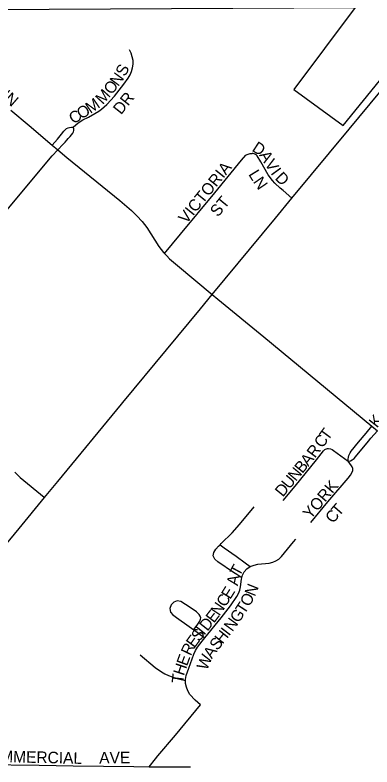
# Model space of a CAD drawing. Extents: x -51392 to 1635000, y 156707 to 696232.
# Drawn here: x 142661 to 144200, y 489969 to 493217 of the extents above; entities that cross this region are included whole.
import ezdxf

# ---------------------------------------------------------------- set-up
doc = ezdxf.new("R2010")
doc.units = 0
for name, color, linetype in [('GM_X_City_Street', 7, 'Continuous'), ('GM_X_City_Street_Text', 7, 'Continuous'), ('GM_X_Corporation', 7, 'Continuous'), ('GM_X_US_Route', 7, 'Continuous')]:
    doc.layers.add(name, color=color, linetype=linetype)

msp = doc.modelspace()

# ---------------------------------------------------------------- linework, layer by layer
at = {"layer": 'GM_X_City_Street'}
for points in [[(142911.9, 492732.6), (142933.5, 492751.4), (142953.3, 492763.8), (142976.8, 492776.3), (143005.2, 492792), (143021.4, 492801.8), (143033.6, 492810.4), (143045.3, 492820), (143056.6, 492830.8), (143089.3, 492866.8), (143129.5, 492917.7), (143148.3, 492944), (143156.4, 492958.1), (143163, 492972.8), (143167.7, 492988.3), (143170.1, 493004.3), (143170, 493013.2), (143169.5, 493020.5), (143166.3, 493036.3), (143160.9, 493051.6), (143154.2, 493066.3)], [(142643.1, 492805.5), (142720.8, 492739.1), (142821.3, 492654.7)], [(142821.3, 492654.7), (142843.4, 492681.1), (142861.3, 492702.6), (142871.2, 492715), (142877.2, 492721.2), (142882.9, 492726.9), (142890.1, 492729.6), (142896, 492731.1), (142904.2, 492732.5), (142911.9, 492732.6)], [(142845.6, 492634.5), (142866.8, 492657.4), (142876.5, 492667.8), (142884.5, 492676.7), (142890.1, 492682.9), (142898.7, 492692.1), (142909.9, 492706.3), (142913, 492712.6), (142913.4, 492718.5), (142913.8, 492725.8), (142911.9, 492732.6)], [(141933.2, 491622.4), (141984, 491665.8), (142095.8, 491762.2), (142156.8, 491817.3), (142191.3, 491852.7), (142245.3, 491914.6), (142422.5, 492129.9), (142610.7, 492357.2), (142821, 492608.8), (142845.6, 492634.5)], [(142821.3, 492654.7), (142845.6, 492634.5)], [(142845.6, 492634.5), (142883.9, 492602.1), (143112.6, 492415.8), (143162.5, 492372.8), (143186.2, 492349.8), (143208.3, 492325.1), (143228.6, 492299.1), (143280.5, 492216.6), (143300.6, 492191.1), (143305.1, 492186.7)], [(143305.1, 492186.7), (143374.5, 492270.2), (143522.4, 492448.9), (143637.5, 492590.5), (143656.3, 492611.4), (143661.2, 492614.6), (143665.7, 492616.6), (143674.3, 492618.8), (143682.8, 492619.1)], [(143854.8, 492426.5), (143816.6, 492458.7), (143804.5, 492468.9), (143781.4, 492490.3), (143771, 492501.9), (143752.6, 492527.2), (143721.1, 492582.7), (143705.1, 492608.1), (143702.1, 492611.7), (143697.8, 492614.7), (143691.9, 492617), (143686.9, 492618.3), (143682.8, 492619.1)], [(143305.1, 492186.7), (143315.1, 492176.9), (143327.1, 492164.6), (143360.9, 492134.7), (143510.6, 492009.8)], [(143510.6, 492009.8), (143535.8, 491989.2), (143734.2, 491826.8), (144199, 491441.5)], [(144097.9, 491289.6), (144097.6, 491299.2), (144098.9, 491307.3), (144100.8, 491315.1), (144105.4, 491325.4), (144110.5, 491333.3), (144141.4, 491371.4), (144175.3, 491410.6), (144199, 491441.5)], [(144199, 491441.5), (144223.7, 491420.8)], [(144097.9, 491289.6), (144107, 491291.7), (144115.2, 491295.4), (144119.2, 491298.1), (144123.7, 491301.7), (144129.1, 491308.4), (144185, 491376.8), (144195.2, 491389.3), (144223.7, 491420.8)], [(143816.4, 491120.2), (143868.8, 491182.3), (143961.1, 491295.7), (143991.2, 491334.1), (143996.7, 491340.2), (143999.6, 491342.2), (144003.8, 491343.7), (144008.3, 491344.5), (144012.7, 491344.8), (144020.6, 491343.5), (144027.9, 491340.7), (144034.2, 491335.8), (144097.9, 491289.6)], [(143936.7, 491025.2), (144010.2, 491115), (144096.8, 491216.3), (144106.9, 491229.2), (144114.8, 491243.1), (144116.8, 491250.4), (144117.2, 491254.2), (144117.2, 491258), (144114.6, 491265.1), (144111.2, 491270.5), (144097.9, 491289.6)], [(142659.2, 491242.7), (142682.9, 491219.7), (142785.5, 491134.7), (142788.1, 491132.6)], [(143544.7, 490929.2), (143549.7, 490934), (143596.9, 490979.9), (143629.2, 491017.2), (143692.3, 491093.3)], [(143675.1, 490835.1), (143675.3, 490835.2), (143691.4, 490841.2), (143708, 490844.5), (143756.5, 490849.7), (143771.7, 490853.3), (143785.8, 490859), (143798.4, 490867.4), (143809.6, 490878.1), (143861, 490941), (143871.6, 490953.4)], [(143638.4, 490786.6), (143616.4, 490800.3), (143602.4, 490808.9), (143534.5, 490855.8), (143521.9, 490866.3), (143514.4, 490880.6), (143518.1, 490896.3), (143526.7, 490910.2), (143537.8, 490922.5), (143544.7, 490929.2)], [(143544.7, 490929.2), (143563, 490916.3), (143614.7, 490879.9), (143652.8, 490851.6), (143675.1, 490835.1)], [(143638.4, 490786.6), (143641.2, 490797), (143649.3, 490812.4), (143660.9, 490825.4), (143675.1, 490835.1)], [(143478.9, 490527.1), (143549.9, 490613.1), (143589.2, 490665), (143616.4, 490705), (143624.4, 490718.7), (143630.2, 490732.9), (143633.5, 490748), (143636.7, 490780.4), (143638.4, 490786.6)], [(143433, 490564.4), (143448.7, 490585.6), (143458, 490598.9), (143460.3, 490607.1), (143461.7, 490613.8), (143460.9, 490617.6), (143459.6, 490620.9), (143454.4, 490627.6), (143442.5, 490638.8), (143416.4, 490658), (143375.6, 490684.3), (143360.1, 490686.5), (143345.2, 490680.6), (143334, 490669.1), (143328.2, 490654), (143330.6, 490638.6), (143340.6, 490626.2), (143367, 490607.5), (143446.1, 490551.7), (143459, 490542), (143478.9, 490527.1)], [(143396.2, 490343.5), (143396.2, 490347.5), (143399.2, 490364.2), (143409.4, 490395.7), (143431.7, 490456.9), (143438.5, 490472.2), (143447, 490486.7), (143467.2, 490512.9), (143478.9, 490527.1)], [(143200.3, 490454.3), (143265.1, 490399.6), (143292.4, 490379.6), (143306.9, 490371), (143322.2, 490363.8), (143338.1, 490358), (143354.3, 490353), (143370.9, 490349.2), (143396.2, 490343.5)], [(143460.7, 490238.1), (143437.2, 490257.6), (143414.1, 490282.8), (143405.4, 490297.5), (143399.3, 490313.5), (143396.1, 490330.4), (143396.2, 490343.5)], [(143239.2, 489970.4), (143266.2, 490003.9), (143276.7, 490016.9), (143352, 490107), (143460.7, 490238.1)], [(142398.3, 489981.2), (142437.9, 489980.9), (142519.6, 489980.1), (142764.5, 489977.3), (142911.3, 489974.7), (143172.6, 489970.8), (143239.2, 489970.4)], [(143239.2, 489970.4), (143417.6, 489969.4)]]:
    msp.add_lwpolyline(points, dxfattribs=at)
at = {"layer": 'GM_X_Corporation'}
msp.add_lwpolyline([(141751.1, 493236.9), (144127.3, 493249.1), (143862.5, 492895), (144076.3, 492740.3), (144496.1, 493256), (147648.1, 493156), (147726.1, 493493.1), (147980.5, 493563.8), (148083.2, 493654.9), (148089.4, 493834.9), (147982, 494020.6), (147817.8, 494131.2), (147642.1, 494222.5), (147459.8, 494299.8), (147362.1, 494455.9), (147137.1, 494480.4), (147057.7, 494609.7), (147023, 494871.5), (147113.7, 495022.6), (147163.6, 495289.2), (147209.8, 495374.5), (147505, 495552.1), (147591.3, 495737.6), (147596.3, 495932.9)], dxfattribs=at)
at = {"layer": 'GM_X_US_Route'}
for points in [[(144101.7, 492724.4), (144233.8, 492883.3), (144409.9, 493099.1), (144480.8, 493185.6), (144490.8, 493197.9), (144521.7, 493235.7)], [(143120.3, 491536.9), (143125.8, 491543.7), (143314.4, 491770.6), (143459.9, 491948.3), (143510.6, 492009.8), (143783.3, 492340.2), (143854.8, 492426.5), (144101.7, 492724.4)], [(142501, 490785.9), (142678, 490999.1), (142788.1, 491132.6), (142844.9, 491201.6), (143120.3, 491536.9)]]:
    msp.add_lwpolyline(points, dxfattribs=at)

# ---------------------------------------------------------------- texts
at = {"layer": 'GM_X_City_Street_Text'}
for s, rotation, p in [('GLENN', 319.0083, (142473.9, 492968.7)), ('S', 62.9186, (143135.6, 492948.6)), ('N', 53.8532, (143105.2, 492905.7)), ('O', 52.1414, (143077.2, 492869.7)), ('M', 47.6986, (143038.9, 492827.4)), ('DR', 51.4416, (143117.8, 492783.6)), ('M', 34.0948, (142985.4, 492789.3)), ('C', 32.3354, (142912.4, 492744)), ('O', 31.3487, (142945.6, 492765)), ('D', 327.194, (143679.1, 492631.9)), ('A', 301.4873, (143712, 492612.3)), ('VICTORIA', 51.0676, (143399.6, 492312.1)), ('V', 302.164, (143735.3, 492574.2)), ('L', 301.6054, (143665.4, 492529.1)), ('I', 305.9526, (143760.8, 492534)), ('D', 314.3592, (143778.9, 492510)), ('N', 304.4186, (143685.3, 492496.9)), ('ST', 50.7401, (143535.7, 492341.8)), ('K', 52.1211, (144221.7, 491430.7)), ('T', 53.6819, (144009.4, 491375.3)), ('C', 53.6698, (143986, 491343.4)), ('R', 53.0431, (143954, 491300.6)), ('A', 50.8559, (143924.9, 491264.9)), ('B', 50.4562, (143899.5, 491234.1)), ('N', 50.4551, (143871.4, 491200.1)), ('U', 50.4447, (143843.4, 491166.2)), ('YORK', 49.7806, (143935.2, 491036.6)), ('D', 50.4588, (143815.4, 491132.3)), ('T', 48.9027, (144057.1, 491048.5)), ('C', 51.1278, (144032.6, 491018.1)), ('T', 61.529, (143628.2, 490789.3)), ('A', 79.2072, (143621.4, 490749.9)), ('E', 57.9522, (143588.3, 490690.2)), ('N', 68.1366, (143694.9, 490702.8)), ('O', 61.2142, (143670.9, 490658.3)), ('C', 57.9384, (143567.3, 490656.6)), ('T', 56.9707, (143649.6, 490625.3)), ('N', 55.7986, (143541.4, 490618.5)), ('E', 52.2465, (143517.9, 490587.9)), ('G', 56.239, (143624.8, 490588.2)), ('D', 51.5312, (143490.1, 490552.9)), ('N', 53.997, (143597.7, 490550.8)), ('S', 51.5759, (143454.5, 490508.1)), ('I', 51.5168, (143476.4, 490535.7)), ('H', 51.4828, (143555.4, 490497)), ('I', 52.4588, (143583.4, 490532.2)), ('E', 53.8381, (143434.1, 490480.1)), ('S', 51.6952, (143533.7, 490469.5)), ('R', 64.549, (143418.3, 490446.5)), ('W', 66.4856, (143487.8, 490383.6)), ('A', 55.6969, (143509.4, 490433.8)), ('E', 69.7874, (143402.1, 490402.2)), ('H', 71.8271, (143388.5, 490360.8)), ('T', 83.444, (143385, 490328.5)), ('COMMERCIAL', 358.7651, (142496, 489992.3)), ('AVE', 0.5386, (143023.8, 489984.1))]:
    msp.add_text(s, height=50, rotation=rotation, dxfattribs=at).set_placement(p)

doc.saveas('drawing.dxf')
